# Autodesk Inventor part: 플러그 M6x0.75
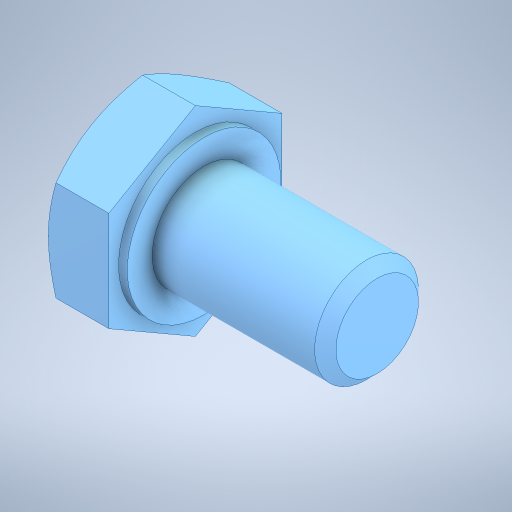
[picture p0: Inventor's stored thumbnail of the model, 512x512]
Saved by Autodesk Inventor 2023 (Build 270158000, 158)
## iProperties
Created: 2026-03
Part Number: 플러그 M6x0.75
Material: 강철, 연강
Description: 6각 머리 볼트 및 6각 머리 나사
Document SubType Name: Modeling
Designer: home
Density: 7.85 g/cm^3
Appearance: 기본값
Author: jhkim
Sending System: Autodesk Inventor 2026
Preprocessor: ST-DEVELOPER v20.1
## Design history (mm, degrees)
feature "Solid1"
node "솔리드1"
